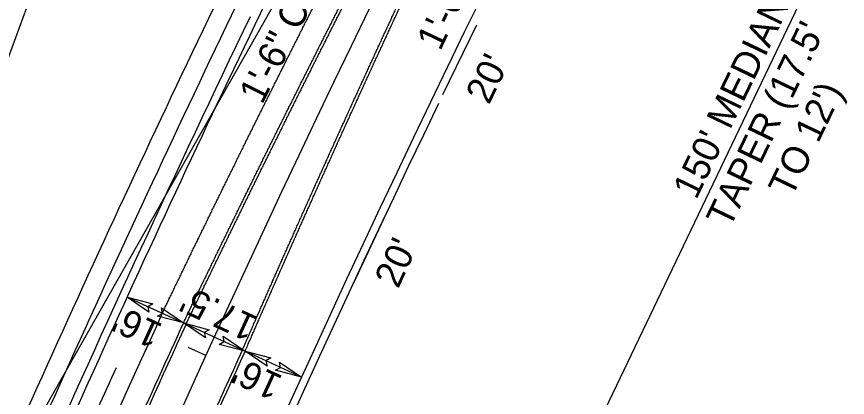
# Model space of a CAD drawing. Extents: x 1974386 to 1979988, y 776712 to 784860.
# Drawn here: x 1977715.8 to 1977930.1, y 781914.3 to 782012.6 of the extents above; entities that cross this region are included whole.
import ezdxf

# ---------------------------------------------------------------- set-up
doc = ezdxf.new("R2010")
doc.units = 0
for name, color, linetype in [('Prop Conc 1ft 6in Curb and Gutter', 7, 'Continuous'), ('Prop Conc 2ft 6in Curb and Gutter', 7, 'Continuous'), ('Prop Conc 4in Sidewalk', 7, 'Continuous'), ('Prop Conc Drive Drop Type', 7, 'Continuous'), ('Prop Dimension', 7, 'Continuous'), ('Prop Dimension Text', 7, 'Continuous'), ('Prop EOT', 7, 'Continuous'), ('Prop Horizontal Alignment', 7, 'Continuous'), ('Prop Horizontal Alignment Station Label', 7, 'Continuous'), ('Prop Horizontal Alignment Tick Small', 7, 'Continuous'), ('Prop Lane Lines', 7, 'Continuous'), ('Prop Terminator CELL', 7, 'Continuous'), ('Scratch_Level_1', 7, 'Continuous')]:
    doc.layers.add(name, color=color, linetype=linetype)

msp = doc.modelspace()

# ---------------------------------------------------------------- linework, layer by layer
at = {"layer": 'Prop Conc 1ft 6in Curb and Gutter'}
for radius in [4208, 4192]:
    msp.add_arc((1981585.24, 780180.82), radius, 155.38997, 156.00754, dxfattribs=at)
for points in [[(1977781.44, 781978.23), (1977781.74, 781978.83), (1977782.04, 781979.44), (1977782.34, 781980.05), (1977782.64, 781980.65), (1977782.94, 781981.26), (1977783.24, 781981.86), (1977783.54, 781982.47), (1977783.85, 781983.08), (1977784.15, 781983.68), (1977784.45, 781984.29), (1977784.75, 781984.9), (1977785.05, 781985.5), (1977785.35, 781986.11), (1977785.65, 781986.71), (1977785.96, 781987.32), (1977786.26, 781987.93), (1977786.56, 781988.53), (1977786.86, 781989.14), (1977787.16, 781989.74), (1977787.47, 781990.35), (1977787.77, 781990.95), (1977788.07, 781991.56), (1977788.37, 781992.17), (1977788.68, 781992.77), (1977788.98, 781993.38), (1977789.28, 781993.98), (1977789.58, 781994.59), (1977789.89, 781995.19), (1977790.19, 781995.8), (1977790.49, 781996.4), (1977790.8, 781997.01), (1977791.1, 781997.61), (1977791.4, 781998.22), (1977791.71, 781998.82), (1977792.01, 781999.43), (1977792.31, 782000.03), (1977792.62, 782000.64), (1977792.92, 782001.24), (1977793.23, 782001.85), (1977793.53, 782002.45), (1977793.84, 782003.06), (1977794.14, 782003.66), (1977794.44, 782004.27), (1977794.75, 782004.87), (1977795.05, 782005.47), (1977795.36, 782006.08), (1977795.66, 782006.68), (1977795.97, 782007.29), (1977796.27, 782007.89), (1977796.58, 782008.5), (1977796.88, 782009.1), (1977797.19, 782009.7), (1977797.49, 782010.31), (1977797.8, 782010.91), (1977798.1, 782011.52), (1977798.41, 782012.12), (1977798.72, 782012.72), (1977799.02, 782013.33), (1977799.33, 782013.93), (1977799.63, 782014.53), (1977799.94, 782015.14), (1977800.25, 782015.74), (1977800.55, 782016.34), (1977800.86, 782016.95), (1977801.17, 782017.55), (1977801.47, 782018.15), (1977801.78, 782018.76), (1977802.09, 782019.36), (1977802.39, 782019.96), (1977802.7, 782020.57), (1977803.01, 782021.17), (1977803.32, 782021.77), (1977803.62, 782022.38), (1977803.93, 782022.98)], [(1977794.25, 781972.17), (1977794.52, 781972.79), (1977794.8, 781973.4), (1977795.08, 781974.02), (1977795.36, 781974.63), (1977795.63, 781975.25), (1977795.91, 781975.86), (1977796.19, 781976.48), (1977796.47, 781977.09), (1977796.74, 781977.71), (1977797.02, 781978.32), (1977797.3, 781978.94), (1977797.58, 781979.55), (1977797.86, 781980.17), (1977798.14, 781980.78), (1977798.41, 781981.4), (1977798.69, 781982.01), (1977798.97, 781982.63), (1977799.25, 781983.24), (1977799.53, 781983.85), (1977799.81, 781984.47), (1977800.09, 781985.08), (1977800.37, 781985.7), (1977800.64, 781986.31), (1977800.92, 781986.93), (1977801.2, 781987.54), (1977801.48, 781988.15), (1977801.76, 781988.77), (1977802.04, 781989.38), (1977802.32, 781990), (1977802.6, 781990.61), (1977802.88, 781991.22), (1977803.16, 781991.84), (1977803.44, 781992.45), (1977803.72, 781993.06), (1977804, 781993.68), (1977804.28, 781994.29), (1977804.56, 781994.91), (1977804.85, 781995.52), (1977805.13, 781996.13), (1977805.41, 781996.75), (1977805.69, 781997.36), (1977805.97, 781997.97), (1977806.25, 781998.59), (1977806.53, 781999.2), (1977806.81, 781999.81), (1977807.09, 782000.43), (1977807.38, 782001.04), (1977807.66, 782001.65), (1977807.94, 782002.26), (1977808.22, 782002.88), (1977808.5, 782003.49), (1977808.79, 782004.1), (1977809.07, 782004.72), (1977809.35, 782005.33), (1977809.63, 782005.94), (1977809.92, 782006.56), (1977810.2, 782007.17), (1977810.48, 782007.78), (1977810.76, 782008.39), (1977811.05, 782009.01), (1977811.33, 782009.62), (1977811.61, 782010.23), (1977811.9, 782010.84), (1977812.18, 782011.46), (1977812.46, 782012.07), (1977812.75, 782012.68), (1977813.03, 782013.29), (1977813.31, 782013.91), (1977813.6, 782014.52), (1977813.88, 782015.13), (1977814.16, 782015.74), (1977814.45, 782016.35), (1977814.73, 782016.97), (1977815.02, 782017.58)], [(1977759.48, 781933.2), (1977759.77, 781933.81), (1977760.06, 781934.42), (1977760.36, 781935.03), (1977760.65, 781935.64), (1977760.95, 781936.25), (1977761.24, 781936.86), (1977761.53, 781937.47), (1977761.83, 781938.08), (1977762.12, 781938.69), (1977762.41, 781939.3), (1977762.71, 781939.91), (1977763, 781940.52), (1977763.3, 781941.13), (1977763.59, 781941.74), (1977763.89, 781942.35), (1977764.18, 781942.96), (1977764.48, 781943.57), (1977764.77, 781944.18), (1977765.07, 781944.79), (1977765.36, 781945.39), (1977765.66, 781946), (1977765.95, 781946.61), (1977766.25, 781947.22), (1977766.54, 781947.83), (1977766.84, 781948.44), (1977767.13, 781949.05), (1977767.43, 781949.66), (1977767.73, 781950.27), (1977768.02, 781950.88), (1977768.32, 781951.49), (1977768.61, 781952.09), (1977768.91, 781952.7), (1977769.21, 781953.31), (1977769.5, 781953.92), (1977769.8, 781954.53), (1977770.1, 781955.14), (1977770.39, 781955.75), (1977770.69, 781956.35), (1977770.99, 781956.96), (1977771.28, 781957.57), (1977771.58, 781958.18), (1977771.88, 781958.79), (1977772.17, 781959.4), (1977772.47, 781960), (1977772.77, 781960.61), (1977773.07, 781961.22), (1977773.36, 781961.83), (1977773.66, 781962.44), (1977773.96, 781963.04), (1977774.26, 781963.65), (1977774.56, 781964.26), (1977774.85, 781964.87), (1977775.15, 781965.48), (1977775.45, 781966.08), (1977775.75, 781966.69), (1977776.05, 781967.3), (1977776.35, 781967.91), (1977776.65, 781968.51), (1977776.94, 781969.12), (1977777.24, 781969.73), (1977777.54, 781970.34), (1977777.84, 781970.94), (1977778.14, 781971.55), (1977778.44, 781972.16), (1977778.74, 781972.76), (1977779.04, 781973.37), (1977779.34, 781973.98), (1977779.64, 781974.59), (1977779.94, 781975.19), (1977780.24, 781975.8), (1977780.54, 781976.41), (1977780.84, 781977.01), (1977781.14, 781977.62), (1977781.44, 781978.23)], [(1977774.02, 781926.53), (1977774.29, 781927.15), (1977774.56, 781927.77), (1977774.83, 781928.39), (1977775.1, 781929.01), (1977775.37, 781929.63), (1977775.64, 781930.24), (1977775.91, 781930.86), (1977776.18, 781931.48), (1977776.46, 781932.1), (1977776.73, 781932.72), (1977777, 781933.33), (1977777.27, 781933.95), (1977777.54, 781934.57), (1977777.81, 781935.19), (1977778.08, 781935.8), (1977778.35, 781936.42), (1977778.62, 781937.04), (1977778.89, 781937.66), (1977779.16, 781938.27), (1977779.44, 781938.89), (1977779.71, 781939.51), (1977779.98, 781940.13), (1977780.25, 781940.74), (1977780.52, 781941.36), (1977780.8, 781941.98), (1977781.07, 781942.6), (1977781.34, 781943.21), (1977781.61, 781943.83), (1977781.88, 781944.45), (1977782.16, 781945.06), (1977782.43, 781945.68), (1977782.7, 781946.3), (1977782.98, 781946.92), (1977783.25, 781947.53), (1977783.52, 781948.15), (1977783.79, 781948.77), (1977784.07, 781949.38), (1977784.34, 781950), (1977784.61, 781950.62), (1977784.89, 781951.23), (1977785.16, 781951.85), (1977785.44, 781952.47), (1977785.71, 781953.08), (1977785.98, 781953.7), (1977786.26, 781954.32), (1977786.53, 781954.93), (1977786.81, 781955.55), (1977787.08, 781956.16), (1977787.35, 781956.78), (1977787.63, 781957.4), (1977787.9, 781958.01), (1977788.18, 781958.63), (1977788.45, 781959.25), (1977788.73, 781959.86), (1977789, 781960.48), (1977789.28, 781961.09), (1977789.55, 781961.71), (1977789.83, 781962.33), (1977790.1, 781962.94), (1977790.38, 781963.56), (1977790.66, 781964.17), (1977790.93, 781964.79), (1977791.21, 781965.4), (1977791.48, 781966.02), (1977791.76, 781966.64), (1977792.04, 781967.25), (1977792.31, 781967.87), (1977792.59, 781968.48), (1977792.86, 781969.1), (1977793.14, 781969.71), (1977793.42, 781970.33), (1977793.69, 781970.94), (1977793.97, 781971.56), (1977794.25, 781972.17)]]:
    msp.add_spline(points, degree=3, dxfattribs=at)
at = {"layer": 'Prop Conc 2ft 6in Curb and Gutter'}
for radius, start, end in [(4226.75, 154.31954, 156.1098), (4173.25, 154.30709, 162.22085)]:
    msp.add_arc((1981585.24, 780180.82), radius, start, end, dxfattribs=at)
at = {"layer": 'Prop Conc 4in Sidewalk'}
for radius in [4236.25, 4231.25]:
    msp.add_arc((1981585.24, 780180.82), radius, 153.35488, 156.1098, dxfattribs=at)
at = {"layer": 'Prop Conc Drive Drop Type'}
for p, q in [((1977834.4, 782010.37), (1977825.68, 781992.37)), ((1977811.08, 781961.73), (1977802.58, 781943.62))]:
    msp.add_line(p, q, dxfattribs=at)
at = {"layer": 'Prop Dimension'}
for p, q in [((1977919.95, 782020.76), (1977856.79, 781888.62)), ((1977744.25, 781940.17), (1977758.8, 781933.51)), ((1977758.8, 781933.51), (1977774.71, 781926.22)), ((1977789.25, 781919.56), (1977774.71, 781926.22))]:
    msp.add_line(p, q, dxfattribs=at)
at = {"layer": 'Prop EOT'}
for centre, radius, start, end in [((1981585.24, 780180.82), 4224.75, 153.3437, 156.10982), ((1981585.79, 780180.59), 4175.85, 153.34433, 162.22022), ((1981585.24, 780180.82), 4208.75, 155.38997, 156.23945), ((1981585.24, 780180.82), 4191.25, 155.38997, 156.23945)]:
    msp.add_arc(centre, radius, start, end, dxfattribs=at)
for points in [[(1977780.76, 781978.55), (1977781.06, 781979.15), (1977781.36, 781979.76), (1977781.66, 781980.37), (1977781.96, 781980.97), (1977782.26, 781981.58), (1977782.57, 781982.19), (1977782.87, 781982.79), (1977783.17, 781983.4), (1977783.47, 781984.01), (1977783.77, 781984.61), (1977784.07, 781985.22), (1977784.37, 781985.82), (1977784.67, 781986.43), (1977784.98, 781987.04), (1977785.28, 781987.64), (1977785.58, 781988.25), (1977785.88, 781988.85), (1977786.18, 781989.46), (1977786.49, 781990.07), (1977786.79, 781990.67), (1977787.09, 781991.28), (1977787.39, 781991.88), (1977787.7, 781992.49), (1977788, 781993.09), (1977788.3, 781993.7), (1977788.6, 781994.3), (1977788.91, 781994.91), (1977789.21, 781995.52), (1977789.51, 781996.12), (1977789.82, 781996.73), (1977790.12, 781997.33), (1977790.42, 781997.94), (1977790.73, 781998.54), (1977791.03, 781999.15), (1977791.33, 781999.75), (1977791.64, 782000.36), (1977791.94, 782000.96), (1977792.25, 782001.57), (1977792.55, 782002.17), (1977792.85, 782002.78), (1977793.16, 782003.38), (1977793.46, 782003.99), (1977793.77, 782004.59), (1977794.07, 782005.19), (1977794.38, 782005.8), (1977794.68, 782006.4), (1977794.99, 782007.01), (1977795.29, 782007.61), (1977795.6, 782008.22), (1977795.9, 782008.82), (1977796.21, 782009.43), (1977796.51, 782010.03), (1977796.82, 782010.63), (1977797.12, 782011.24), (1977797.43, 782011.84), (1977797.74, 782012.45), (1977798.04, 782013.05), (1977798.35, 782013.65), (1977798.65, 782014.26), (1977798.96, 782014.86), (1977799.27, 782015.46), (1977799.57, 782016.07), (1977799.88, 782016.67), (1977800.19, 782017.28), (1977800.49, 782017.88), (1977800.8, 782018.48), (1977801.11, 782019.09), (1977801.41, 782019.69), (1977801.72, 782020.29), (1977802.03, 782020.9), (1977802.33, 782021.5), (1977802.64, 782022.1), (1977802.95, 782022.7), (1977803.26, 782023.31)], [(1977794.93, 781971.85), (1977795.2, 781972.47), (1977795.48, 781973.08), (1977795.76, 781973.7), (1977796.03, 781974.31), (1977796.31, 781974.93), (1977796.59, 781975.54), (1977796.87, 781976.16), (1977797.14, 781976.77), (1977797.42, 781977.39), (1977797.7, 781978), (1977797.98, 781978.62), (1977798.26, 781979.23), (1977798.53, 781979.85), (1977798.81, 781980.46), (1977799.09, 781981.07), (1977799.37, 781981.69), (1977799.65, 781982.3), (1977799.93, 781982.92), (1977800.21, 781983.53), (1977800.48, 781984.15), (1977800.76, 781984.76), (1977801.04, 781985.37), (1977801.32, 781985.99), (1977801.6, 781986.6), (1977801.88, 781987.22), (1977802.16, 781987.83), (1977802.44, 781988.44), (1977802.72, 781989.06), (1977803, 781989.67), (1977803.28, 781990.29), (1977803.56, 781990.9), (1977803.84, 781991.51), (1977804.12, 781992.13), (1977804.4, 781992.74), (1977804.68, 781993.35), (1977804.96, 781993.97), (1977805.24, 781994.58), (1977805.52, 781995.19), (1977805.8, 781995.81), (1977806.08, 781996.42), (1977806.36, 781997.03), (1977806.65, 781997.65), (1977806.93, 781998.26), (1977807.21, 781998.87), (1977807.49, 781999.49), (1977807.77, 782000.1), (1977808.05, 782000.71), (1977808.33, 782001.33), (1977808.62, 782001.94), (1977808.9, 782002.55), (1977809.18, 782003.17), (1977809.46, 782003.78), (1977809.74, 782004.39), (1977810.03, 782005), (1977810.31, 782005.62), (1977810.59, 782006.23), (1977810.87, 782006.84), (1977811.16, 782007.45), (1977811.44, 782008.07), (1977811.72, 782008.68), (1977812, 782009.29), (1977812.29, 782009.9), (1977812.57, 782010.52), (1977812.85, 782011.13), (1977813.14, 782011.74), (1977813.42, 782012.35), (1977813.7, 782012.97), (1977813.99, 782013.58), (1977814.27, 782014.19), (1977814.56, 782014.8), (1977814.84, 782015.41), (1977815.12, 782016.03), (1977815.41, 782016.64), (1977815.69, 782017.25)], [(1977758.8, 781933.51), (1977759.09, 781934.12), (1977759.38, 781934.73), (1977759.68, 781935.34), (1977759.97, 781935.95), (1977760.26, 781936.56), (1977760.56, 781937.17), (1977760.85, 781937.78), (1977761.15, 781938.39), (1977761.44, 781939), (1977761.73, 781939.61), (1977762.03, 781940.22), (1977762.32, 781940.83), (1977762.62, 781941.44), (1977762.91, 781942.05), (1977763.21, 781942.66), (1977763.5, 781943.27), (1977763.8, 781943.88), (1977764.09, 781944.49), (1977764.39, 781945.1), (1977764.68, 781945.71), (1977764.98, 781946.32), (1977765.27, 781946.93), (1977765.57, 781947.54), (1977765.86, 781948.15), (1977766.16, 781948.76), (1977766.45, 781949.36), (1977766.75, 781949.97), (1977767.04, 781950.58), (1977767.34, 781951.19), (1977767.64, 781951.8), (1977767.93, 781952.41), (1977768.23, 781953.02), (1977768.53, 781953.63), (1977768.82, 781954.24), (1977769.12, 781954.84), (1977769.42, 781955.45), (1977769.71, 781956.06), (1977770.01, 781956.67), (1977770.31, 781957.28), (1977770.6, 781957.89), (1977770.9, 781958.5), (1977771.2, 781959.1), (1977771.49, 781959.71), (1977771.79, 781960.32), (1977772.09, 781960.93), (1977772.39, 781961.54), (1977772.69, 781962.15), (1977772.98, 781962.75), (1977773.28, 781963.36), (1977773.58, 781963.97), (1977773.88, 781964.58), (1977774.18, 781965.19), (1977774.47, 781965.79), (1977774.77, 781966.4), (1977775.07, 781967.01), (1977775.37, 781967.62), (1977775.67, 781968.22), (1977775.97, 781968.83), (1977776.27, 781969.44), (1977776.56, 781970.05), (1977776.86, 781970.65), (1977777.16, 781971.26), (1977777.46, 781971.87), (1977777.76, 781972.48), (1977778.06, 781973.08), (1977778.36, 781973.69), (1977778.66, 781974.3), (1977778.96, 781974.9), (1977779.26, 781975.51), (1977779.56, 781976.12), (1977779.86, 781976.73), (1977780.16, 781977.33), (1977780.46, 781977.94), (1977780.76, 781978.55)], [(1977774.71, 781926.22), (1977774.98, 781926.84), (1977775.25, 781927.46), (1977775.52, 781928.08), (1977775.79, 781928.7), (1977776.06, 781929.31), (1977776.33, 781929.93), (1977776.6, 781930.55), (1977776.87, 781931.17), (1977777.14, 781931.78), (1977777.41, 781932.4), (1977777.68, 781933.02), (1977777.95, 781933.64), (1977778.22, 781934.26), (1977778.49, 781934.87), (1977778.76, 781935.49), (1977779.03, 781936.11), (1977779.3, 781936.73), (1977779.57, 781937.34), (1977779.85, 781937.96), (1977780.12, 781938.58), (1977780.39, 781939.2), (1977780.66, 781939.81), (1977780.93, 781940.43), (1977781.2, 781941.05), (1977781.48, 781941.66), (1977781.75, 781942.28), (1977782.02, 781942.9), (1977782.29, 781943.52), (1977782.57, 781944.13), (1977782.84, 781944.75), (1977783.11, 781945.37), (1977783.38, 781945.98), (1977783.66, 781946.6), (1977783.93, 781947.22), (1977784.2, 781947.83), (1977784.47, 781948.45), (1977784.75, 781949.07), (1977785.02, 781949.68), (1977785.29, 781950.3), (1977785.57, 781950.92), (1977785.84, 781951.53), (1977786.12, 781952.15), (1977786.39, 781952.77), (1977786.66, 781953.38), (1977786.94, 781954), (1977787.21, 781954.61), (1977787.49, 781955.23), (1977787.76, 781955.85), (1977788.03, 781956.46), (1977788.31, 781957.08), (1977788.58, 781957.7), (1977788.86, 781958.31), (1977789.13, 781958.93), (1977789.41, 781959.54), (1977789.68, 781960.16), (1977789.96, 781960.77), (1977790.23, 781961.39), (1977790.51, 781962.01), (1977790.78, 781962.62), (1977791.06, 781963.24), (1977791.33, 781963.85), (1977791.61, 781964.47), (1977791.89, 781965.08), (1977792.16, 781965.7), (1977792.44, 781966.32), (1977792.71, 781966.93), (1977792.99, 781967.55), (1977793.27, 781968.16), (1977793.54, 781968.78), (1977793.82, 781969.39), (1977794.1, 781970.01), (1977794.37, 781970.62), (1977794.65, 781971.24), (1977794.93, 781971.85)]]:
    msp.add_spline(points, degree=3, dxfattribs=at)
at = {"layer": 'Prop Horizontal Alignment'}
msp.add_arc((1981585.24, 780180.82), 4200, 153.11985, 162.22085, dxfattribs=at)
at = {"layer": 'Prop Horizontal Alignment Station Label'}
msp.add_line((1977685.36, 781925.2), (1977721.81, 782024.2), dxfattribs=at)
at = {"layer": 'Prop Horizontal Alignment Tick Small'}
msp.add_line((1977764.56, 781925.07), (1977760.01, 781927.15), dxfattribs=at)
at = {"layer": 'Prop Lane Lines'}
msp.add_arc((1981585.24, 780180.82), 4219.75, 155.63077, 156.26125, dxfattribs=at)
at = {"layer": 'Prop Terminator CELL'}
for points in [[(1977749.9, 781936.31), (1977744.25, 781940.17), (1977750.92, 781938.44), (1977749.64, 781937.71)], [(1977753.14, 781937.38), (1977758.8, 781933.51), (1977752.13, 781935.25), (1977753.41, 781935.98)], [(1977764.45, 781929.64), (1977758.8, 781933.51), (1977765.47, 781931.77), (1977764.18, 781931.04)], [(1977769.05, 781930.09), (1977774.71, 781926.22), (1977768.04, 781927.96), (1977769.32, 781928.69)], [(1977780.36, 781922.35), (1977774.71, 781926.22), (1977781.38, 781924.49), (1977780.09, 781923.76)], [(1977783.6, 781923.43), (1977789.25, 781919.56), (1977782.58, 781921.3), (1977783.87, 781922.03)]]:
    msp.add_lwpolyline(points, close=True, dxfattribs=at)
at = {"layer": 'Scratch_Level_1'}
msp.add_line((1977884.79, 782196.56), (1977671.06, 781820.03), dxfattribs=at)
msp.add_arc((1981585.24, 780180.82), 4214.75, 155.38997, 157.26808, dxfattribs=at)
for points in [[(1977775.38, 781981.21), (1977775.68, 781981.82), (1977775.99, 781982.42), (1977776.29, 781983.03), (1977776.59, 781983.64), (1977776.89, 781984.25), (1977777.19, 781984.85), (1977777.49, 781985.46), (1977777.79, 781986.07), (1977778.1, 781986.68), (1977778.4, 781987.28), (1977778.7, 781987.89), (1977779, 781988.5), (1977779.3, 781989.1), (1977779.61, 781989.71), (1977779.91, 781990.32), (1977780.21, 781990.92), (1977780.51, 781991.53), (1977780.81, 781992.14), (1977781.12, 781992.74), (1977781.42, 781993.35), (1977781.72, 781993.96), (1977782.03, 781994.56), (1977782.33, 781995.17), (1977782.63, 781995.78), (1977782.94, 781996.38), (1977783.24, 781996.99), (1977783.54, 781997.6), (1977783.85, 781998.2), (1977784.15, 781998.81), (1977784.45, 781999.41), (1977784.76, 782000.02), (1977785.06, 782000.63), (1977785.36, 782001.23), (1977785.67, 782001.84), (1977785.97, 782002.44), (1977786.28, 782003.05), (1977786.58, 782003.66), (1977786.89, 782004.26), (1977787.19, 782004.87), (1977787.49, 782005.47), (1977787.8, 782006.08), (1977788.1, 782006.68), (1977788.41, 782007.29), (1977788.71, 782007.89), (1977789.02, 782008.5), (1977789.32, 782009.11), (1977789.63, 782009.71), (1977789.94, 782010.32), (1977790.24, 782010.92), (1977790.55, 782011.53), (1977790.85, 782012.13), (1977791.16, 782012.74), (1977791.46, 782013.34), (1977791.77, 782013.95), (1977792.08, 782014.55), (1977792.38, 782015.16), (1977792.69, 782015.76), (1977793, 782016.37), (1977793.3, 782016.97), (1977793.61, 782017.57), (1977793.92, 782018.18), (1977794.22, 782018.78), (1977794.53, 782019.39), (1977794.84, 782019.99), (1977795.14, 782020.6), (1977795.45, 782021.2), (1977795.76, 782021.81), (1977796.06, 782022.41), (1977796.37, 782023.01), (1977796.68, 782023.62), (1977796.99, 782024.22), (1977797.3, 782024.83), (1977797.6, 782025.43), (1977797.91, 782026.03)], [(1977753.39, 781936.11), (1977753.68, 781936.72), (1977753.98, 781937.33), (1977754.27, 781937.94), (1977754.56, 781938.55), (1977754.86, 781939.16), (1977755.15, 781939.78), (1977755.45, 781940.39), (1977755.74, 781941), (1977756.03, 781941.61), (1977756.33, 781942.22), (1977756.62, 781942.83), (1977756.92, 781943.44), (1977757.21, 781944.05), (1977757.51, 781944.66), (1977757.8, 781945.27), (1977758.1, 781945.88), (1977758.39, 781946.49), (1977758.69, 781947.1), (1977758.98, 781947.71), (1977759.28, 781948.32), (1977759.58, 781948.93), (1977759.87, 781949.54), (1977760.17, 781950.16), (1977760.46, 781950.77), (1977760.76, 781951.38), (1977761.06, 781951.99), (1977761.35, 781952.6), (1977761.65, 781953.21), (1977761.94, 781953.82), (1977762.24, 781954.42), (1977762.54, 781955.03), (1977762.83, 781955.64), (1977763.13, 781956.25), (1977763.43, 781956.86), (1977763.73, 781957.47), (1977764.02, 781958.08), (1977764.32, 781958.69), (1977764.62, 781959.3), (1977764.91, 781959.91), (1977765.21, 781960.52), (1977765.51, 781961.13), (1977765.81, 781961.74), (1977766.1, 781962.35), (1977766.4, 781962.96), (1977766.7, 781963.57), (1977767, 781964.18), (1977767.3, 781964.78), (1977767.6, 781965.39), (1977767.89, 781966), (1977768.19, 781966.61), (1977768.49, 781967.22), (1977768.79, 781967.83), (1977769.09, 781968.44), (1977769.39, 781969.05), (1977769.69, 781969.65), (1977769.98, 781970.26), (1977770.28, 781970.87), (1977770.58, 781971.48), (1977770.88, 781972.09), (1977771.18, 781972.7), (1977771.48, 781973.31), (1977771.78, 781973.91), (1977772.08, 781974.52), (1977772.38, 781975.13), (1977772.68, 781975.74), (1977772.98, 781976.35), (1977773.28, 781976.95), (1977773.58, 781977.56), (1977773.88, 781978.17), (1977774.18, 781978.78), (1977774.48, 781979.39), (1977774.78, 781979.99), (1977775.08, 781980.6), (1977775.38, 781981.21)]]:
    msp.add_spline(points, degree=3, dxfattribs=at)

# ---------------------------------------------------------------- texts
at = {"layer": 'Prop Dimension'}
for s, rotation, p in [('1\'-6" C&G', 64.737, (1977825.04, 782003.47)), ('1\'-6" C&G', 63.3535, (1977779.1, 781989.66)), ("20'", 64.1638, (1977837.63, 781989.62)), ("20'", 65.367, (1977814.2, 781942.14))]:
    msp.add_text(s, height=7, rotation=rotation, dxfattribs=at).set_placement(p)
at = {"layer": 'Prop Dimension Text'}
for s, rotation, p in [("150' MEDIAN", 64.2887, (1977891.11, 781965.11)), ("TAPER (17.5'", 64.2887, (1977899.74, 781957.68)), ("TO 12')", 64.2887, (1977915.77, 781965.62)), ("17.5'", 155.3902, (1977778.37, 781934.86)), ("16'", 155.3902, (1977753.81, 781933.01)), ("16'", 155.3902, (1977784.76, 781919.66))]:
    msp.add_text(s, height=7, rotation=rotation, dxfattribs=at).set_placement(p)

doc.saveas('drawing.dxf')
